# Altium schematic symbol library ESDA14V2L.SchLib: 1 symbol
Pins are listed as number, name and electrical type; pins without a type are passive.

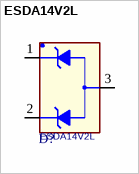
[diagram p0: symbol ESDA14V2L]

## ESDA14V2L
designator D?
footprint ST_SOT23-3L
pins: 1 K1, 2 K2, 3 A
